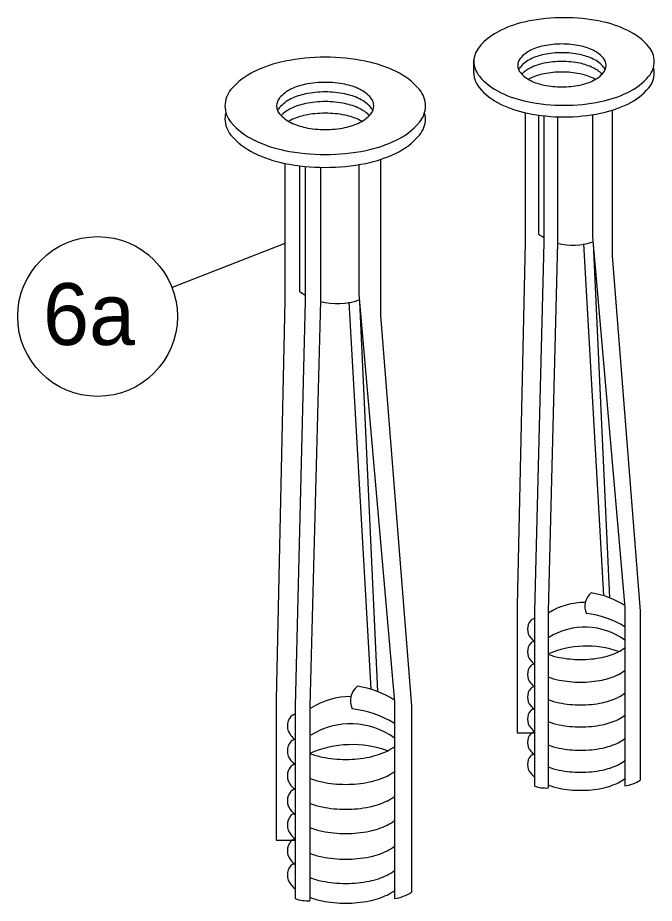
# Model space of a CAD drawing. Extents: x 12.3 to 19.6, y 5.8 to 16.1.
# Drawn here: x 12.782 to 13.664, y 7.533 to 8.761 of the extents above; entities that cross this region are included whole.
import ezdxf

# ---------------------------------------------------------------- set-up
doc = ezdxf.new("R2010")
doc.units = 0
doc.layers.add('DETL-LINE', color=7, linetype='Continuous')
doc.layers.add('DETL-NOTE', color=7, linetype='Continuous')

msp = doc.modelspace()

# ---------------------------------------------------------------- linework, layer by layer
at = {"layer": 'DETL-LINE'}
for p, q in [((13.4143, 8.6844), (13.4144, 8.7029)), ((13.4852, 8.6295), (13.4852, 8.4494)), ((13.5042, 8.4609), (13.5042, 8.6261)), ((13.5111, 8.6252), (13.5111, 8.4494)), ((13.5303, 8.6238), (13.5303, 8.4494)), ((13.5786, 8.6267), (13.5786, 8.4574)), ((13.606, 8.6328), (13.606, 8.4308)), ((13.2848, 8.5645), (13.2848, 8.3482)), ((13.1519, 8.5591), (13.1519, 8.3687)), ((13.1727, 8.3814), (13.1727, 8.5557)), ((13.1804, 8.5549), (13.1804, 8.3687)), ((13.2015, 8.5536), (13.2015, 8.3687)), ((13.2546, 8.5574), (13.2546, 8.3775)), ((13.4852, 8.4494), (13.4744, 7.946)), ((13.5111, 8.4494), (13.4984, 7.9381)), ((13.5303, 8.4494), (13.5171, 7.9381)), ((13.5786, 8.4574), (13.6237, 7.9434)), ((13.5661, 8.4475), (13.5938, 7.9597)), ((13.5795, 8.448), (13.6021, 7.9568)), ((13.606, 8.4308), (13.645, 7.9381)), ((13.2546, 8.3775), (13.3042, 7.8121)), ((13.1519, 8.3687), (13.14, 7.815)), ((13.1804, 8.3687), (13.1664, 7.8062)), ((13.2015, 8.3687), (13.1869, 7.8062)), ((13.2409, 8.3666), (13.2713, 7.83)), ((13.2555, 8.3672), (13.2804, 7.8269)), ((13.2848, 8.3482), (13.3276, 7.8062)), ((13.4744, 7.946), (13.4744, 7.7692)), ((13.4984, 7.9381), (13.4984, 7.6957)), ((13.5171, 7.9381), (13.5171, 7.693)), ((13.6237, 7.9434), (13.6237, 7.6957)), ((13.645, 7.9381), (13.645, 7.7037)), ((13.14, 7.815), (13.14, 7.6205)), ((13.3042, 7.8121), (13.3042, 7.5396)), ((13.1664, 7.8062), (13.1664, 7.5396)), ((13.1869, 7.8062), (13.1869, 7.5367)), ((13.3276, 7.8062), (13.3276, 7.5484)), ((13.4744, 7.7692), (13.4984, 7.7692)), ((13.14, 7.6205), (13.1664, 7.6205))]:
    msp.add_line(p, q, dxfattribs=at)
for centre, radius, start, end in [((13.5394, 8.5043), 0.2569, 90, 101.3709), ((13.5394, 8.5043), 0.2569, 78.6291, 90), ((13.5198, 8.6015), 0.1577, 101.3709, 115.8973), ((13.5589, 8.6015), 0.1577, 64.1027, 78.6291), ((13.4902, 8.6626), 0.0898, 115.8973, 139.5312), ((13.5886, 8.6626), 0.0898, 40.4688, 64.1027), ((13.4458, 8.7004), 0.0315, 139.5312, 180), ((13.5268, 8.6464), 0.0774, 101.3557, 115.8664), ((13.5364, 8.5986), 0.1261, 90, 101.3557), ((13.5364, 8.5986), 0.1261, 78.6443, 90), ((13.5459, 8.6464), 0.0774, 64.1336, 78.6443), ((13.6329, 8.7004), 0.0315, 360, 40.4688), ((13.5122, 8.6764), 0.044, 115.8664, 139.4922), ((13.5268, 8.6342), 0.0774, 101.3557, 115.8664), ((13.5364, 8.5865), 0.1261, 90, 101.3557), ((13.5364, 8.5865), 0.1261, 78.6443, 90), ((13.5459, 8.6342), 0.0774, 64.1336, 78.6443), ((13.5605, 8.6764), 0.044, 40.5078, 64.1336), ((13.1864, 8.5289), 0.1752, 101.3709, 115.8973), ((13.2081, 8.4209), 0.2854, 90, 101.3709), ((13.2081, 8.4209), 0.2854, 78.6291, 90), ((13.2298, 8.5289), 0.1752, 64.1027, 78.6291), ((13.4458, 8.7004), 0.0315, 180, 220.4688), ((13.4904, 8.695), 0.0154, 139.4922, 180), ((13.5122, 8.6642), 0.044, 115.8664, 139.4922), ((13.5268, 8.6221), 0.0774, 101.3557, 115.8664), ((13.5364, 8.5743), 0.1261, 90, 101.3557), ((13.5364, 8.5743), 0.1261, 78.6443, 90), ((13.5459, 8.6221), 0.0774, 64.1336, 78.6443), ((13.5605, 8.6642), 0.044, 40.5078, 64.1336), ((13.5823, 8.695), 0.0154, 360, 40.5078), ((13.6329, 8.7004), 0.0315, 319.5312, 0), ((13.1534, 8.5968), 0.0998, 115.8973, 139.5312), ((13.2628, 8.5968), 0.0998, 40.4688, 64.1027), ((13.4458, 8.6844), 0.0315, 180, 220.4688), ((13.4904, 8.695), 0.0154, 180, 220.5078), ((13.4904, 8.6828), 0.0154, 139.4922, 156.7461), ((13.5122, 8.7136), 0.044, 220.5078, 244.1336), ((13.5122, 8.6521), 0.044, 115.8664, 135.6907), ((13.5268, 8.6075), 0.0774, 101.3557, 115.8664), ((13.5364, 8.5597), 0.1261, 90, 101.3557), ((13.5364, 8.5597), 0.1261, 78.6443, 90), ((13.5459, 8.6075), 0.0774, 64.1336, 78.6443), ((13.5605, 8.6521), 0.044, 44.3093, 64.1336), ((13.5605, 8.7136), 0.044, 295.8664, 319.4922), ((13.5823, 8.695), 0.0154, 319.4922, 0), ((13.5823, 8.6828), 0.0154, 23.2539, 40.5078), ((13.6329, 8.6844), 0.0315, 319.5312, 0), ((13.6329, 8.6844), 0.0315, 360, 14.7634), ((13.2081, 8.5328), 0.1387, 90, 101.3557), ((13.2081, 8.5328), 0.1387, 78.6443, 90), ((13.4902, 8.7383), 0.0898, 220.4688, 244.1027), ((13.5122, 8.6375), 0.044, 115.8664, 120.2074), ((13.5268, 8.7436), 0.0774, 244.1336, 258.6443), ((13.5459, 8.7436), 0.0774, 281.3557, 295.8664), ((13.5605, 8.6375), 0.044, 59.7926, 64.1336), ((13.5886, 8.7383), 0.0898, 295.8973, 319.5312), ((13.1041, 8.6388), 0.035, 139.5312, 180), ((13.1816, 8.6184), 0.0484, 115.8664, 139.4922), ((13.1976, 8.5854), 0.0851, 101.3557, 115.8664), ((13.2187, 8.5854), 0.0851, 64.1336, 78.6443), ((13.2347, 8.6184), 0.0484, 40.5078, 64.1336), ((13.3121, 8.6388), 0.035, 0, 40.4688), ((13.4902, 8.7222), 0.0898, 220.4688, 244.1027), ((13.5364, 8.7913), 0.1261, 258.6443, 270), ((13.5364, 8.7913), 0.1261, 270, 281.3557), ((13.5886, 8.7222), 0.0898, 295.8973, 319.5312), ((13.1576, 8.6388), 0.0169, 139.4922, 180), ((13.1816, 8.605), 0.0484, 115.8664, 139.4922), ((13.1976, 8.572), 0.0851, 101.3557, 115.8664), ((13.2081, 8.5195), 0.1387, 90, 101.3557), ((13.2081, 8.5195), 0.1387, 78.6443, 90), ((13.2187, 8.572), 0.0851, 64.1336, 78.6443), ((13.2347, 8.605), 0.0484, 40.5078, 64.1336), ((13.2586, 8.6388), 0.0169, 360, 40.5078), ((13.5198, 8.7994), 0.1577, 244.1027, 258.6291), ((13.5589, 8.7994), 0.1577, 281.3709, 295.8973), ((13.1041, 8.6388), 0.035, 180, 220.4688), ((13.1576, 8.6388), 0.0169, 180, 220.5078), ((13.1576, 8.6255), 0.0169, 139.4922, 156.7461), ((13.1816, 8.5916), 0.0484, 115.8664, 135.6907), ((13.1976, 8.5586), 0.0851, 101.3557, 115.8664), ((13.2081, 8.5061), 0.1387, 90, 101.3557), ((13.2081, 8.5061), 0.1387, 78.6443, 90), ((13.2187, 8.5586), 0.0851, 64.1336, 78.6443), ((13.2347, 8.5916), 0.0484, 44.3093, 64.1336), ((13.2586, 8.6388), 0.0169, 319.4922, 0), ((13.2586, 8.6255), 0.0169, 23.2539, 40.5078), ((13.3121, 8.6388), 0.035, 319.5312, 360), ((13.5198, 8.7833), 0.1577, 244.1027, 258.6291), ((13.5394, 8.8966), 0.2569, 258.6291, 270), ((13.5394, 8.8966), 0.2569, 270, 281.3709), ((13.5589, 8.7833), 0.1577, 281.3709, 295.8973), ((13.1041, 8.621), 0.035, 165.2366, 180), ((13.1816, 8.6593), 0.0484, 220.5078, 244.1336), ((13.1976, 8.5426), 0.0851, 101.3557, 115.8664), ((13.2081, 8.49), 0.1387, 90, 101.3557), ((13.2081, 8.49), 0.1387, 78.6443, 90), ((13.2187, 8.5426), 0.0851, 64.1336, 78.6443), ((13.2347, 8.6593), 0.0484, 295.8664, 319.4922), ((13.3121, 8.621), 0.035, 0, 14.7634), ((13.5394, 8.8805), 0.2569, 258.6291, 270), ((13.5394, 8.8805), 0.2569, 270, 281.3709), ((13.1041, 8.621), 0.035, 180, 220.4688), ((13.1534, 8.6809), 0.0998, 220.4688, 244.1027), ((13.1816, 8.5756), 0.0484, 115.8664, 120.2074), ((13.1976, 8.6923), 0.0851, 244.1336, 258.6443), ((13.2187, 8.6923), 0.0851, 281.3557, 295.8664), ((13.2347, 8.5756), 0.0484, 59.7926, 64.1336), ((13.2628, 8.6809), 0.0998, 295.8973, 319.5312), ((13.3121, 8.621), 0.035, 319.5312, 360), ((13.1534, 8.6631), 0.0998, 220.4688, 244.1027), ((13.2081, 8.7448), 0.1387, 258.6443, 270), ((13.2081, 8.7448), 0.1387, 270, 281.3557), ((13.2628, 8.6631), 0.0998, 295.8973, 319.5312), ((13.1864, 8.7488), 0.1752, 244.1027, 258.6291), ((13.2298, 8.7488), 0.1752, 281.3709, 295.8973), ((13.1864, 8.7309), 0.1752, 244.1027, 258.6291), ((13.2081, 8.8568), 0.2854, 258.6291, 270), ((13.2081, 8.8568), 0.2854, 270, 281.3709), ((13.2298, 8.7309), 0.1752, 281.3709, 295.8973), ((13.2081, 8.839), 0.2854, 258.6291, 270), ((13.2081, 8.839), 0.2854, 270, 281.3709), ((13.552, 8.5282), 0.0825, 234.6116, 240.3143), ((13.552, 8.5282), 0.0825, 254.7883, 289.3036), ((13.2253, 8.4554), 0.0908, 234.6116, 240.3143), ((13.2253, 8.4554), 0.0908, 254.7883, 289.3036), ((13.5925, 7.9449), 0.0243, 129.9978, 204.8964), ((13.5584, 7.8429), 0.122, 57.6772, 81.3099), ((13.5682, 7.8565), 0.0938, 89.658, 122.2181), ((13.5584, 7.8133), 0.122, 57.6772, 84.3464), ((13.5071, 7.9133), 0.0185, 139.4922, 180), ((13.5333, 7.891), 0.0528, 138.7828, 139.4922), ((13.5069, 7.9041), 0.0255, 109.4731, 121.692), ((13.5071, 7.9133), 0.0185, 180, 220.5078), ((13.5682, 7.8222), 0.0938, 53.7599, 122.2181), ((13.5333, 7.9356), 0.0528, 220.5078, 228.7285), ((13.5071, 7.8818), 0.0185, 139.4922, 180), ((13.5333, 7.8595), 0.0528, 138.7828, 139.4922), ((13.5069, 7.8726), 0.0255, 109.4731, 121.692), ((13.5703, 7.7572), 0.1326, 70.2819, 113.692), ((13.5912, 7.9291), 0.0528, 295.8664, 307.9171), ((13.5071, 7.8818), 0.0185, 180, 220.5078), ((13.5507, 7.9651), 0.0929, 248.7495, 258.6443), ((13.5622, 8.0224), 0.1513, 258.6443, 270), ((13.5622, 8.0224), 0.1513, 270, 281.3557), ((13.5737, 7.9651), 0.0929, 281.3557, 295.8664), ((13.5071, 7.8503), 0.0185, 139.4922, 180), ((13.5333, 7.9041), 0.0528, 220.5078, 228.7285), ((13.5333, 7.828), 0.0528, 138.7828, 139.4922), ((13.5069, 7.8412), 0.0255, 109.4731, 121.692), ((13.5071, 7.8503), 0.0185, 180, 220.5078), ((13.5737, 7.9337), 0.0929, 281.3557, 295.8664), ((13.5912, 7.8976), 0.0528, 295.8664, 307.9171), ((13.5333, 7.8726), 0.0528, 220.5078, 228.7285), ((13.5507, 7.9337), 0.0929, 248.7495, 258.6443), ((13.5622, 7.991), 0.1513, 258.6443, 270), ((13.5622, 7.991), 0.1513, 270, 281.3557), ((13.2699, 7.8138), 0.0267, 129.9978, 204.8964), ((13.2324, 7.7015), 0.1342, 57.6772, 81.3099), ((13.5071, 7.8189), 0.0185, 139.4922, 180), ((13.5333, 7.7965), 0.0528, 138.7828, 139.4922), ((13.5069, 7.8097), 0.0255, 109.4731, 121.692), ((13.5912, 7.8662), 0.0528, 295.8664, 307.9171), ((13.2432, 7.7165), 0.1032, 89.658, 122.2181), ((13.5071, 7.8189), 0.0185, 180, 220.5078), ((13.5507, 7.9022), 0.0929, 248.7495, 258.6443), ((13.5622, 7.9595), 0.1513, 258.6443, 270), ((13.5622, 7.9595), 0.1513, 270, 281.3557), ((13.5737, 7.9022), 0.0929, 281.3557, 295.8664), ((13.2324, 7.669), 0.1342, 57.6772, 84.3464), ((13.5071, 7.7883), 0.0185, 139.4922, 180), ((13.5333, 7.8412), 0.0528, 220.5078, 228.7285), ((13.5333, 7.766), 0.0528, 138.7828, 139.4922), ((13.5069, 7.7791), 0.0255, 109.4731, 121.692), ((13.176, 7.779), 0.0203, 139.4922, 180), ((13.2047, 7.7544), 0.0581, 138.7828, 139.4922), ((13.1757, 7.7689), 0.028, 109.4731, 121.692), ((13.5071, 7.7883), 0.0185, 180, 220.5078), ((13.5737, 7.8716), 0.0929, 281.3557, 295.8664), ((13.5912, 7.8356), 0.0528, 295.8664, 307.9171), ((13.176, 7.779), 0.0203, 180, 220.5078), ((13.2432, 7.6788), 0.1032, 53.7599, 122.2181), ((13.5333, 7.8106), 0.0528, 220.5078, 228.7285), ((13.5507, 7.8716), 0.0929, 248.7495, 258.6443), ((13.5622, 7.9289), 0.1513, 258.6443, 270), ((13.5622, 7.9289), 0.1513, 270, 281.3557), ((13.2047, 7.8035), 0.0581, 220.5078, 228.7285), ((13.5071, 7.7559), 0.0185, 139.4922, 180), ((13.5333, 7.7336), 0.0528, 138.7828, 139.4922), ((13.5069, 7.7467), 0.0255, 109.4731, 121.692), ((13.176, 7.7443), 0.0203, 139.4922, 180), ((13.2047, 7.7198), 0.0581, 138.7828, 139.4922), ((13.1757, 7.7342), 0.028, 109.4731, 121.692), ((13.2455, 7.6072), 0.1459, 70.2819, 113.692), ((13.2685, 7.7964), 0.0581, 295.8664, 307.9171), ((13.5071, 7.7559), 0.0185, 180, 220.5078), ((13.5507, 7.8392), 0.0929, 248.7495, 258.6443), ((13.5737, 7.8392), 0.0929, 281.3557, 295.8664), ((13.5912, 7.8032), 0.0528, 295.8664, 307.9171), ((13.176, 7.7443), 0.0203, 180, 220.5078), ((13.2239, 7.836), 0.1021, 248.7495, 258.6443), ((13.2493, 7.836), 0.1021, 281.3557, 295.8664), ((13.5071, 7.7254), 0.0185, 139.4922, 180), ((13.5333, 7.7782), 0.0528, 220.5078, 228.7285), ((13.5333, 7.7031), 0.0528, 138.7828, 139.4922), ((13.5069, 7.7162), 0.0255, 109.4731, 121.692), ((13.5622, 7.8966), 0.1513, 258.6443, 270), ((13.5622, 7.8966), 0.1513, 270, 281.3557), ((13.2047, 7.7689), 0.0581, 220.5078, 228.7285), ((13.1757, 7.6996), 0.028, 109.4731, 121.692), ((13.2366, 7.899), 0.1664, 258.6443, 270), ((13.2366, 7.899), 0.1664, 270, 281.3557), ((13.5071, 7.7254), 0.0185, 180, 220.5078), ((13.5737, 7.8087), 0.0929, 281.3557, 295.8664), ((13.5912, 7.7727), 0.0528, 295.8664, 307.9171), ((13.176, 7.7097), 0.0203, 139.4922, 180), ((13.2047, 7.6852), 0.0581, 138.7828, 139.4922), ((13.2685, 7.7618), 0.0581, 295.8664, 307.9171), ((13.5333, 7.7477), 0.0528, 220.5078, 228.7285), ((13.5507, 7.8087), 0.0929, 248.7495, 258.6443), ((13.5622, 7.866), 0.1513, 258.6443, 270), ((13.5622, 7.866), 0.1513, 270, 281.3557), ((13.176, 7.7097), 0.0203, 180, 220.5078), ((13.2239, 7.8014), 0.1021, 248.7495, 258.6443), ((13.2366, 7.8644), 0.1664, 258.6443, 270), ((13.2366, 7.8644), 0.1664, 270, 281.3557), ((13.2493, 7.8014), 0.1021, 281.3557, 295.8664), ((13.5912, 7.7477), 0.0528, 295.8664, 307.9171), ((13.6172, 7.7455), 0.0502, 277.441, 303.6474), ((13.176, 7.6751), 0.0203, 139.4922, 180), ((13.2047, 7.7343), 0.0581, 220.5078, 228.7285), ((13.2047, 7.6506), 0.0581, 138.7828, 139.4922), ((13.1757, 7.665), 0.028, 109.4731, 121.692), ((13.514, 7.7383), 0.0454, 249.9032, 273.8465), ((13.5507, 7.7837), 0.0929, 248.7495, 258.6443), ((13.5622, 7.841), 0.1513, 258.6443, 270), ((13.5622, 7.841), 0.1513, 270, 281.3557), ((13.5737, 7.7837), 0.0929, 281.3557, 295.8664), ((13.2685, 7.7271), 0.0581, 295.8664, 307.9171), ((13.176, 7.6751), 0.0203, 180, 220.5078), ((13.2239, 7.7668), 0.1021, 248.7495, 258.6443), ((13.2366, 7.8298), 0.1664, 258.6443, 270), ((13.2366, 7.8298), 0.1664, 270, 281.3557), ((13.2493, 7.7668), 0.1021, 281.3557, 295.8664), ((13.176, 7.6415), 0.0203, 139.4922, 180), ((13.2047, 7.6997), 0.0581, 220.5078, 228.7285), ((13.2047, 7.617), 0.0581, 138.7828, 139.4922), ((13.1757, 7.6314), 0.028, 109.4731, 121.692), ((13.176, 7.6415), 0.0203, 180, 220.5078), ((13.2493, 7.7332), 0.1021, 281.3557, 295.8664), ((13.2685, 7.6935), 0.0581, 295.8664, 307.9171), ((13.2047, 7.6661), 0.0581, 220.5078, 228.7285), ((13.2239, 7.7332), 0.1021, 248.7495, 258.6443), ((13.2366, 7.7962), 0.1664, 258.6443, 270), ((13.2366, 7.7962), 0.1664, 270, 281.3557), ((13.176, 7.6059), 0.0203, 139.4922, 180), ((13.2047, 7.5813), 0.0581, 138.7828, 139.4922), ((13.1757, 7.5958), 0.028, 109.4731, 121.692), ((13.176, 7.6059), 0.0203, 180, 220.5078), ((13.2239, 7.6975), 0.1021, 248.7495, 258.6443), ((13.2493, 7.6975), 0.1021, 281.3557, 295.8664), ((13.2685, 7.6579), 0.0581, 295.8664, 307.9171), ((13.2047, 7.6304), 0.0581, 220.5078, 228.7285), ((13.2366, 7.7606), 0.1664, 258.6443, 270), ((13.2366, 7.7606), 0.1664, 270, 281.3557), ((13.176, 7.5723), 0.0203, 139.4922, 180), ((13.2047, 7.5477), 0.0581, 138.7828, 139.4922), ((13.1757, 7.5622), 0.028, 109.4731, 121.692), ((13.2685, 7.6243), 0.0581, 295.8664, 307.9171), ((13.176, 7.5723), 0.0203, 180, 220.5078), ((13.2239, 7.6639), 0.1021, 248.7495, 258.6443), ((13.2493, 7.6639), 0.1021, 281.3557, 295.8664), ((13.2047, 7.5968), 0.0581, 220.5078, 228.7285), ((13.2366, 7.727), 0.1664, 258.6443, 270), ((13.2366, 7.727), 0.1664, 270, 281.3557), ((13.2239, 7.6364), 0.1021, 248.7495, 258.6443), ((13.2493, 7.6364), 0.1021, 281.3557, 295.8664), ((13.2685, 7.5968), 0.0581, 295.8664, 307.9171), ((13.297, 7.5944), 0.0552, 277.441, 303.6474), ((13.1836, 7.5865), 0.05, 249.9032, 273.8465), ((13.2366, 7.6995), 0.1664, 258.6443, 270), ((13.2366, 7.6995), 0.1664, 270, 281.3557)]:
    msp.add_arc(centre, radius, start, end, dxfattribs=at)
at = {"layer": 'DETL-NOTE'}
msp.add_line((13.1519, 8.4482), (12.9957, 8.3869), dxfattribs=at)
msp.add_circle((12.8925, 8.3468), 0.1108, dxfattribs=at)

# ---------------------------------------------------------------- texts
msp.add_text('6a', height=0.0858, dxfattribs=at).set_placement((12.8168, 8.3073))

doc.saveas('drawing.dxf')
